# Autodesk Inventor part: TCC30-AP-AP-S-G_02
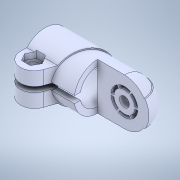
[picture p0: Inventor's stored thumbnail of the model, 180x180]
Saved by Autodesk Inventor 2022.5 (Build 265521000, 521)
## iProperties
Created: 2023-09
Part Number: TCC30-AP-AP-S-G_02
Material: 一般
Document SubType Name: Modeling
Designer: ImaoCorp
Density: 1 g/cm^3
Appearance: 既定
Author: ImaoCorp
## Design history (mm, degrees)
feature "TCC30-AP-AP-S-G_02"
node "ソリッド1"
